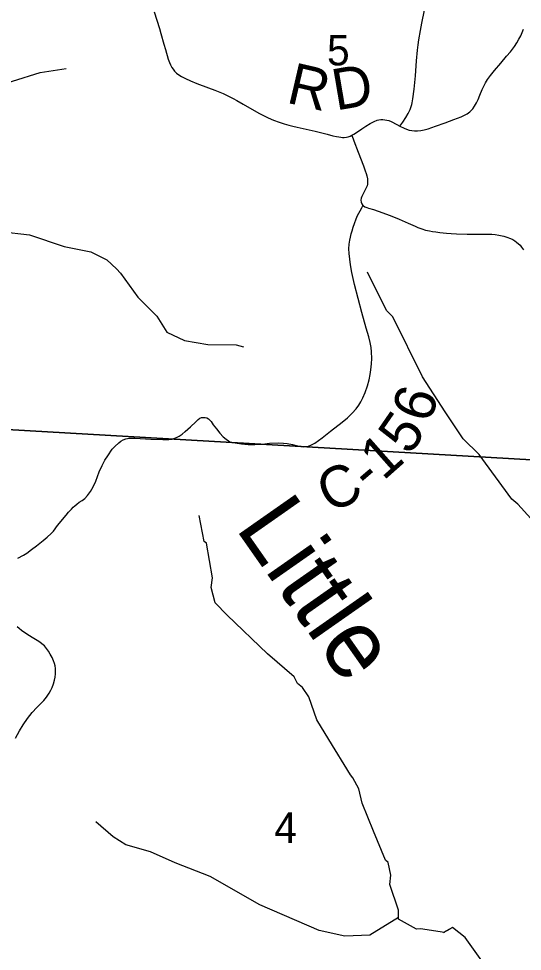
# Model space of a CAD drawing. Extents: x 0 to 34, y 0 to 22.
# Drawn here: x 6.258 to 6.952, y 16.555 to 17.839 of the extents above; entities that cross this region are included whole.
import ezdxf

# ---------------------------------------------------------------- set-up
doc = ezdxf.new("R2010")
doc.units = 0
for name, color, linetype in [('GM_X_County_Road', 7, 'Continuous'), ('GM_X_County_Road_Text', 7, 'Continuous'), ('GM_X_Minor_River', 7, 'Continuous'), ('GM_X_Minor_River_Text', 7, 'Continuous'), ('GM_X_Section', 7, 'Continuous'), ('GM_X_Section_Text', 7, 'Continuous'), ('GM_X_Township_Road', 7, 'Continuous')]:
    doc.layers.add(name, color=color, linetype=linetype)

msp = doc.modelspace()

# ---------------------------------------------------------------- linework, layer by layer
at = {"layer": 'GM_X_County_Road'}
for points in [[(6.4449, 17.8483), (6.4521, 17.8252), (6.454, 17.8186), (6.4584, 17.8038), (6.4604, 17.7966), (6.4644, 17.7829), (6.466, 17.7786), (6.4675, 17.7752), (6.4693, 17.7716), (6.471, 17.7692), (6.473, 17.7667), (6.4758, 17.764), (6.4788, 17.7617), (6.4825, 17.7593), (6.488, 17.7563), (6.4948, 17.7531), (6.5035, 17.7495), (6.5198, 17.7435), (6.5285, 17.7404), (6.5353, 17.7377), (6.5397, 17.7359), (6.5464, 17.7328), (6.5535, 17.7291), (6.5588, 17.7261), (6.5673, 17.721), (6.5792, 17.7141), (6.5901, 17.7081), (6.5962, 17.705), (6.6018, 17.7024), (6.6092, 17.6993), (6.6168, 17.6964), (6.6238, 17.694), (6.6304, 17.6921), (6.6357, 17.6908), (6.6418, 17.6895), (6.6502, 17.6877), (6.6584, 17.6859), (6.6663, 17.6841), (6.6737, 17.6822), (6.6832, 17.6797), (6.6908, 17.6777), (6.696, 17.6765), (6.699, 17.676), (6.702, 17.6757), (6.7043, 17.6755), (6.7064, 17.6755), (6.7096, 17.6758), (6.7121, 17.6764), (6.7146, 17.6773), (6.717, 17.6783), (6.7199, 17.6798), (6.7235, 17.6821), (6.7305, 17.6872), (6.7361, 17.691), (6.7424, 17.6947), (6.7479, 17.6975), (6.7519, 17.699), (6.7542, 17.6995), (6.7569, 17.6999), (6.7598, 17.7), (6.7625, 17.6998), (6.7651, 17.6993), (6.7678, 17.6987), (6.7712, 17.6972), (6.7789, 17.6933), (6.7832, 17.691), (6.7888, 17.6881), (6.7923, 17.6866), (6.796, 17.6855), (6.7997, 17.6847), (6.8034, 17.6844), (6.8073, 17.6845), (6.8117, 17.6849), (6.8163, 17.6858), (6.8221, 17.6874), (6.8321, 17.6908), (6.8452, 17.6956), (6.8573, 17.7), (6.8673, 17.7038), (6.8722, 17.706), (6.8757, 17.7079), (6.8777, 17.7093), (6.8795, 17.7108), (6.8815, 17.7127), (6.8833, 17.7148), (6.8858, 17.7184), (6.8883, 17.7231), (6.8906, 17.7277), (6.8931, 17.7336), (6.8964, 17.7414), (6.8984, 17.7457), (6.9011, 17.7506), (6.9038, 17.755), (6.9077, 17.7605), (6.9131, 17.7675), (6.9218, 17.7778), (6.9298, 17.787), (6.9352, 17.7934), (6.9406, 17.8007), (6.944, 17.8057), (6.947, 17.8104), (6.9495, 17.8153), (6.9515, 17.82), (6.9532, 17.8244)], [(6.717, 17.6783), (6.7198, 17.6709), (6.7258, 17.6549), (6.7331, 17.6364), (6.7355, 17.6295), (6.7367, 17.6258), (6.7375, 17.6226), (6.7383, 17.6184), (6.7386, 17.6161), (6.7386, 17.6136), (6.7384, 17.6112), (6.7379, 17.6088), (6.7357, 17.6042), (6.7335, 17.5998), (6.732, 17.597), (6.7306, 17.5942), (6.7297, 17.5918), (6.7294, 17.589), (6.7298, 17.5861), (6.7307, 17.5839), (6.7317, 17.5825), (6.7324, 17.5818), (6.7331, 17.5812), (6.7349, 17.58), (6.7374, 17.5789), (6.7401, 17.5781), (6.7467, 17.5761), (6.753, 17.574), (6.7646, 17.5699), (6.7722, 17.567), (6.7823, 17.5629), (6.7945, 17.5575), (6.804, 17.5533), (6.8079, 17.5516), (6.8131, 17.5496), (6.8185, 17.548), (6.8237, 17.5469), (6.8278, 17.546), (6.8327, 17.5453), (6.8382, 17.5446), (6.8472, 17.5438), (6.8538, 17.5432), (6.8608, 17.5429), (6.8756, 17.5425), (6.8899, 17.5424), (6.9055, 17.5423), (6.9095, 17.5421), (6.9142, 17.5417), (6.9194, 17.5409), (6.9259, 17.5395), (6.9301, 17.5383), (6.9352, 17.5364), (6.9383, 17.5349), (6.9413, 17.5332), (6.9436, 17.5314), (6.9484, 17.5271), (6.9505, 17.5244), (6.9533, 17.5206)], [(6.2574, 17.0963), (6.2651, 17.1008), (6.2697, 17.1035), (6.2763, 17.1084), (6.2832, 17.1134), (6.2922, 17.1206), (6.2975, 17.1253), (6.3032, 17.1306), (6.3065, 17.1338), (6.312, 17.1414), (6.3237, 17.1557), (6.3269, 17.1599), (6.331, 17.1639), (6.3336, 17.1666), (6.3357, 17.1687), (6.3387, 17.1709), (6.3417, 17.1733), (6.3458, 17.1759), (6.3496, 17.1786), (6.3534, 17.1826), (6.3574, 17.1881), (6.361, 17.1945), (6.3645, 17.2024), (6.3694, 17.2151), (6.3733, 17.2239), (6.3771, 17.2312), (6.381, 17.2375), (6.3873, 17.2464), (6.3906, 17.2501), (6.3961, 17.2553), (6.3991, 17.2576), (6.4024, 17.2594), (6.406, 17.2607), (6.4103, 17.2614), (6.414, 17.2616), (6.4183, 17.2615), (6.4402, 17.2601), (6.4568, 17.2596), (6.4613, 17.2597), (6.4653, 17.2597), (6.4697, 17.2603), (6.4722, 17.2611), (6.4755, 17.2625), (6.4793, 17.2643), (6.4836, 17.2671), (6.4878, 17.2707), (6.495, 17.2774), (6.5024, 17.2842), (6.5054, 17.2872), (6.5079, 17.289), (6.5101, 17.2898), (6.5127, 17.2901), (6.5151, 17.29), (6.5173, 17.2895), (6.5196, 17.2883), (6.5217, 17.2865), (6.5233, 17.2844), (6.5263, 17.2799), (6.5305, 17.2744), (6.5351, 17.2686), (6.5401, 17.2632), (6.5438, 17.26), (6.5474, 17.2577), (6.5502, 17.2563), (6.5529, 17.2556), (6.5564, 17.255), (6.5649, 17.2536), (6.5742, 17.2529), (6.5835, 17.2528), (6.5939, 17.2535), (6.6038, 17.2545), (6.6167, 17.255), (6.6229, 17.2548), (6.6278, 17.2543), (6.6351, 17.2529), (6.6405, 17.2516), (6.6469, 17.2501), (6.6505, 17.2497), (6.654, 17.2499), (6.6575, 17.2506), (6.6614, 17.2522), (6.6662, 17.2549), (6.676, 17.2622), (6.6875, 17.2711), (6.7037, 17.2836), (6.7108, 17.2896), (6.7175, 17.296), (6.7228, 17.3021), (6.7264, 17.307), (6.7293, 17.3117), (6.7321, 17.3169), (6.7353, 17.3246), (6.7384, 17.3336), (6.7406, 17.3417), (6.7423, 17.3493), (6.7433, 17.3557), (6.7441, 17.3637), (6.7446, 17.3714), (6.7441, 17.3805), (6.7436, 17.3863), (6.7424, 17.3934), (6.7404, 17.401), (6.7368, 17.413), (6.7308, 17.4346), (6.7258, 17.4539), (6.7208, 17.473), (6.717, 17.4897), (6.7151, 17.5001), (6.714, 17.508), (6.7133, 17.5155), (6.7129, 17.5223), (6.7132, 17.5286), (6.7141, 17.5339), (6.7149, 17.5381), (6.716, 17.5427), (6.7173, 17.5469), (6.7188, 17.5517), (6.7206, 17.5569), (6.7229, 17.5633), (6.7248, 17.5678), (6.7282, 17.5743), (6.7306, 17.5786), (6.7317, 17.5805), (6.7324, 17.5818)], [(6.2543, 16.8487), (6.2596, 16.8588), (6.2645, 16.867), (6.2706, 16.8758), (6.2772, 16.884), (6.2836, 16.8909), (6.293, 16.9006), (6.2969, 16.9054), (6.3006, 16.9107), (6.3028, 16.9148), (6.3046, 16.9185), (6.3066, 16.9234), (6.308, 16.9285), (6.3086, 16.9329), (6.3091, 16.9374), (6.3092, 16.9414), (6.3091, 16.9448), (6.3086, 16.9482), (6.3078, 16.9515), (6.3066, 16.9552), (6.3044, 16.9599), (6.3019, 16.9645), (6.2995, 16.9684), (6.2967, 16.9723), (6.2938, 16.9757), (6.2905, 16.9788), (6.2875, 16.9811), (6.284, 16.9833), (6.2772, 16.9874), (6.2699, 16.9919), (6.2624, 16.997), (6.259, 16.9995), (6.2563, 17.0021)]]:
    msp.add_lwpolyline(points, dxfattribs=at)
at = {"layer": 'GM_X_Minor_River'}
for points in [[(5.9029, 17.5141), (5.9362, 17.5229), (5.963, 17.5431), (5.9721, 17.5549), (5.983, 17.5611), (6.0165, 17.6095), (6.0558, 17.6472), (6.0931, 17.6808), (6.1506, 17.7142), (6.2498, 17.7526), (6.2881, 17.7646), (6.3237, 17.7701)], [(6.2335, 17.5461), (6.2734, 17.5414), (6.3213, 17.5251), (6.3577, 17.5178), (6.3797, 17.5069), (6.3933, 17.4947), (6.3984, 17.4884), (6.4224, 17.4558), (6.4488, 17.4295), (6.4625, 17.4074), (6.4867, 17.396), (6.519, 17.3904), (6.5579, 17.3899), (6.5677, 17.3873)], [(6.9766, 17.1362), (6.9452, 17.1706), (6.9371, 17.1777), (6.8924, 17.2391), (6.87, 17.2607), (6.8455, 17.2979), (6.8144, 17.346), (6.7734, 17.4286), (6.7646, 17.4372), (6.7386, 17.4901)], [(6.8444, 16.5814), (6.8116, 16.5864), (6.806, 16.5861), (6.7814, 16.5997), (6.781, 16.6122), (6.7692, 16.6475), (6.7707, 16.6605), (6.7669, 16.6779), (6.7632, 16.681), (6.7469, 16.7208), (6.731, 16.7592), (6.7268, 16.7789), (6.7184, 16.7941), (6.715, 16.7983), (6.6851, 16.8469), (6.6689, 16.8742), (6.6579, 16.9057), (6.6492, 16.9186), (6.642, 16.9239), (6.6378, 16.933), (6.6011, 16.9649), (6.5455, 17.018), (6.5288, 17.035), (6.5235, 17.0559), (6.5254, 17.0696), (6.517, 17.1171), (6.5136, 17.1194), (6.5068, 17.1554)], [(6.781, 16.602), (6.7419, 16.5776), (6.7071, 16.5764), (6.6718, 16.584), (6.5905, 16.6196), (6.5221, 16.6586), (6.4736, 16.6773), (6.44, 16.6924), (6.4059, 16.7022), (6.3885, 16.713), (6.3645, 16.7335)], [(7.1484, 16.3335), (7.1264, 16.3481), (7.09, 16.3792), (7.07, 16.394), (7.0424, 16.4277), (7.0393, 16.4281), (7.0076, 16.4691), (6.9815, 16.4827), (6.9637, 16.4986), (6.9535, 16.5032), (6.9542, 16.5058), (6.9198, 16.5221), (6.9024, 16.5414), (6.896, 16.5426), (6.8729, 16.5744), (6.8555, 16.5884), (6.8433, 16.5816), (6.8522, 16.5865)]]:
    msp.add_lwpolyline(points, dxfattribs=at)
at = {"layer": 'GM_X_Section'}
for points in [[(6.1942, 18.2962), (7.2546, 18.2574), (7.1862, 17.219), (6.1312, 17.2799)], [(7.1862, 17.219), (7.123, 16.2082), (6.0647, 16.248), (6.0651, 16.2532), (6.0768, 16.4347), (6.1041, 16.8596), (6.1312, 17.2799)]]:
    msp.add_lwpolyline(points, close=True, dxfattribs=at)
at = {"layer": 'GM_X_Township_Road'}
msp.add_lwpolyline([(6.7832, 17.691), (6.7871, 17.6963), (6.7912, 17.7026), (6.7944, 17.7081), (6.797, 17.7137), (6.7985, 17.7178), (6.7993, 17.7205), (6.7999, 17.7232), (6.8009, 17.7287), (6.8027, 17.7416), (6.8045, 17.7601), (6.8061, 17.7808), (6.8075, 17.7954), (6.8084, 17.8029), (6.8093, 17.8095), (6.8113, 17.8224), (6.8133, 17.8328), (6.8171, 17.8504)], dxfattribs=at)

# ---------------------------------------------------------------- texts
at = {"layer": 'GM_X_County_Road_Text'}
for s, rotation, p in [('R', 346.8887, (6.6254, 17.7236)), ('D', 9.6833, (6.695, 17.7123)), ('6', 71.0324, (6.8238, 17.2805)), ('5', 55.3666, (6.7963, 17.2366)), ('1', 41.5097, (6.7602, 17.2022)), ('C', 26.6261, (6.6874, 17.1572)), ('-', 40.4737, (6.7416, 17.1864))]:
    msp.add_text(s, height=0.0568, rotation=rotation, dxfattribs=at).set_placement(p)
at = {"layer": 'GM_X_Minor_River_Text'}
msp.add_text('Little', height=0.09469, rotation=304.9993, dxfattribs=at).set_placement((6.5556, 17.1383))
at = {"layer": 'GM_X_Section_Text'}
for s, p in [('5', (6.6828, 17.7745)), ('4', (6.6103, 16.7047))]:
    msp.add_text(s, height=0.0419, rotation=0, dxfattribs=at).set_placement(p)

doc.saveas('drawing.dxf')
